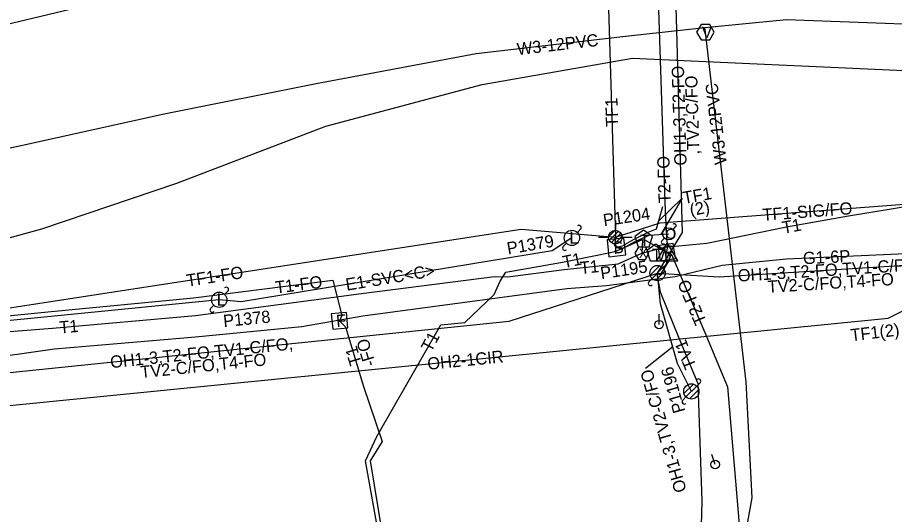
# Model space of a CAD drawing. Extents: x 2336688 to 2352634, y 362473 to 369571.
# Drawn here: x 2351896.3 to 2352182.9, y 368798.3 to 368960.9 of the extents above; entities that cross this region are included whole.
import ezdxf

# ---------------------------------------------------------------- set-up
doc = ezdxf.new("R2010")
doc.units = 0
for name, color, linetype in [('RD_EX_DV_Prop', 7, 'Continuous'), ('RD_EX_DV_TX_Prop', 7, 'Continuous'), ('RD_EX_RW', 7, 'Continuous'), ('RD_EX_RW_TX', 7, 'Continuous'), ('RD_HC_CL_Rel', 7, 'Continuous'), ('RD_HC_Data_Tic', 7, 'Continuous'), ('RD_PD_CstnLmt', 7, 'Continuous'), ('RD_PD_Final_TrvlWay', 7, 'Continuous'), ('RD_PD_FOC', 7, 'Continuous'), ('RD_PD_PatLn2', 7, 'Continuous'), ('RD_PD_PatLn3', 7, 'Continuous'), ('RD_PD_PatLn4', 7, 'Continuous'), ('RD_SHT_ShtClip', 7, 'Continuous'), ('RD_Sketch2', 7, 'Continuous'), ('RD_Sketch5', 7, 'Continuous'), ('RD_Sketch8', 7, 'Continuous')]:
    doc.layers.add(name, color=color, linetype=linetype)

# ---------------------------------------------------------------- blocks, each defined once
blk = doc.blocks.new('GW')
at = {"layer": 'RD_HC_Data_Tic'}
blk.add_line((0, 0), (0, 5), dxfattribs=at)
blk.add_circle((0, 0), 2, dxfattribs=at)

msp = doc.modelspace()

# ---------------------------------------------------------------- linework, layer by layer
at = {"layer": 'RD_EX_RW_TX'}
for points in [[(2352001.58, 369492.45), (2352004.02, 369485.34), (2352012.81, 369439.77), (2352023.11, 369388.83), (2352034.68, 369342.96), (2352043.16, 369279.52), (2352050.69, 369242.38), (2352066.16, 369196.28), (2352079.88, 369147.58), (2352091.56, 369098.6), (2352098.41, 369047.57), (2352103.47, 369016.03), (2352103.73, 369007.69), (2352104.69, 368996.59), (2352107.92, 368897.46), (2352108.57, 368885.58), (2352108.45, 368884.09), (2352110.04, 368883.31), (2352120.9, 368857.81), (2352128.32, 368840.02), (2352133.08, 368783.49)], [(2351885, 368956.88), (2351939.56, 368969.89), (2351988.67, 368980.31), (2352043.04, 368991.24), (2352066.63, 368994.3), (2352086.86, 368995.79), (2352106.62, 368995.87), (2352143.1, 368996.58), (2352187.05, 368996.47), (2352234.49, 368995.02), (2352286.43, 368988.83), (2352336.53, 368982.42)], [(2351854.2, 368855.12), (2351907.65, 368859.27), (2351954.44, 368863.43), (2352008.74, 368870.56), (2352052.2, 368876.14), (2352056.52, 368876.05), (2352074.96, 368878.4), (2352092.6, 368880.26), (2352100.36, 368883.74), (2352107.85, 368885.7), (2352121.63, 368887.01), (2352147.59, 368892.36), (2352167.89, 368895.99), (2352195.79, 368900.53), (2352207.22, 368898.3), (2352213.66, 368891.52), (2352214.78, 368891.59), (2352220.15, 368883.78), (2352239.13, 368881.83), (2352262.16, 368878.52), (2352280.21, 368877.05), (2352321.83, 368870.98)], [(2352023.04, 368743.58), (2352018.61, 368767.78), (2352010.03, 368815.88), (2352013.76, 368823.78), (2352034.6, 368860.37), (2352042.45, 368861.06), (2352052.12, 368870.24), (2352054.08, 368874.63), (2352055.88, 368877.58), (2352074.45, 368880.8), (2352091.57, 368884.28), (2352100.52, 368888.27), (2352100.36, 368883.74)], [(2352100.92, 368888.33), (2352108.45, 368884.09), (2352109.44, 368882.94), (2352109.39, 368881.68), (2352106.38, 368876.68), (2352105.46, 368877.27)], [(2352105.46, 368877.27), (2352105.38, 368876.27), (2352106.29, 368871.12), (2352112.27, 368856.3), (2352118.64, 368841.19), (2352119.94, 368802.65), (2352118.78, 368759.27), (2352108.98, 368715.07), (2352112.43, 368676.89), (2352115.93, 368641.39), (2352118.07, 368629.84), (2352126.4, 368618.98), (2352131.04, 368594.27), (2352141.76, 368542.92), (2352153.06, 368495.22), (2352164.89, 368441.51), (2352174.56, 368395.19)], [(2351800.26, 368708.59), (2351783.98, 368756.59), (2351767.48, 368792.11), (2351762.88, 368809.69), (2351759.04, 368825.42), (2351758.66, 368825.96), (2351759.26, 368827.23), (2351756.66, 368842.63), (2351785.44, 368848.99), (2351806.34, 368852.99), (2351854.03, 368859.38), (2351906.18, 368864.55), (2351953.78, 368869.16), (2351999.38, 368874.93), (2352002.29, 368863.43), (2352001.55, 368861.67), (2352003.47, 368859.64), (2352009.35, 368840.16), (2352015.45, 368822.2), (2352011.56, 368815.85), (2352019.33, 368768.13), (2352023.49, 368743.71)]]:
    msp.add_lwpolyline(points, dxfattribs=at)
for points in [[(2352100.92, 368891.33), (2352098.06, 368889.25), (2352099.15, 368885.9), (2352102.68, 368885.9), (2352103.77, 368889.25)], [(2352102.67, 368883.74), (2352101.51, 368885.74), (2352099.2, 368885.74), (2352098.05, 368883.74), (2352099.2, 368881.74), (2352101.51, 368881.74)], [(2352104.87, 368886.7), (2352102.02, 368884.63), (2352103.11, 368881.27), (2352106.64, 368881.27), (2352107.73, 368884.63)], [(2352110.56, 368886.93), (2352105.61, 368886.2), (2352106.34, 368881.25), (2352111.29, 368881.99)], [(2352003.82, 368864.38), (2351998.84, 368863.94), (2351999.28, 368858.96), (2352004.26, 368859.4)]]:
    msp.add_lwpolyline(points, close=True, dxfattribs=at)
at = {"layer": 'RD_HC_CL_Rel'}
msp.add_lwpolyline([(2351856.12, 368845.07), (2351908.31, 368852.47), (2351954.47, 368856.39), (2351989.24, 368859.76), (2352009.1, 368863.3), (2352075.82, 368872.25), (2352088.74, 368873.22), (2352101.35, 368874.84), (2352111.2, 368876.2), (2352126.61, 368879.82), (2352147.61, 368881.9), (2352189.06, 368883.81), (2352195.59, 368883.03), (2352218.93, 368879.85), (2352230.72, 368877.21), (2352252.22, 368875.78), (2352261.65, 368875.52), (2352280.31, 368872.79), (2352320.53, 368866.38)], dxfattribs=at)
at = {"layer": 'RD_HC_Data_Tic'}
for p, q in [((2352091.68, 368894.52), (2352091.68, 368891.24)), ((2352079.26, 368890.55), (2352080.32, 368891.61)), ((2352089.47, 368889.16), (2352091.55, 368891.24)), ((2352089.72, 368887.99), (2352092.71, 368890.99)), ((2352090.37, 368887.23), (2352093.47, 368890.33)), ((2352110.54, 368891.52), (2352111.38, 368892.37)), ((2352086.15, 368889.02), (2352089.46, 368889.02)), ((2352091.38, 368886.83), (2352093.88, 368889.32)), ((2352093.9, 368889.03), (2352097.21, 368889.03)), ((2352106.86, 368887.84), (2352107.71, 368888.69)), ((2352074.66, 368885.95), (2352075.72, 368887.01)), ((2352091.68, 368886.81), (2352091.68, 368883.52)), ((2352103.05, 368876.63), (2352106.11, 368879.69)), ((2352103.7, 368875.51), (2352107.23, 368879.04)), ((2352107.23, 368879.04), (2352108.29, 368880.1)), ((2352104.82, 368874.86), (2352107.88, 368877.92)), ((2352102.64, 368874.44), (2352103.7, 368875.51)), ((2351963.96, 368870.3), (2351965.02, 368871.36)), ((2351959.36, 368865.71), (2351960.42, 368866.77)), ((2352114.11, 368837.9), (2352117.17, 368840.96)), ((2352114.75, 368836.78), (2352118.29, 368840.31)), ((2352115.87, 368836.13), (2352118.94, 368839.19)), ((2352118.29, 368840.31), (2352119.35, 368841.37)), ((2352113.69, 368835.71), (2352114.75, 368836.78))]:
    msp.add_line(p, q, dxfattribs=at)
for centre, radius in [((2352077.49, 368888.78), 2.5), ((2352091.68, 368889.02), 2.22), ((2352109.12, 368890.1), 2), ((2352105.46, 368877.27), 2.5), ((2351962.19, 368868.54), 2.5), ((2352116.52, 368838.54), 2.5)]:
    msp.add_circle(centre, radius, dxfattribs=at)
for centre, radius, start, end in [((2352110.96, 368892.79), 0.6, 315, 135), ((2352079.79, 368892.14), 0.75, 315, 135), ((2352107.28, 368887.42), 0.6, 135, 315), ((2352075.19, 368885.42), 0.75, 135, 315), ((2352107.76, 368880.63), 0.75, 315, 135), ((2352103.17, 368873.91), 0.75, 135, 315), ((2351964.49, 368871.89), 0.75, 315, 135), ((2351959.89, 368865.18), 0.75, 135, 315), ((2352118.82, 368841.9), 0.75, 315, 135), ((2352114.22, 368835.18), 0.75, 135, 315)]:
    msp.add_arc(centre, radius, start, end, dxfattribs=at)
at = {"layer": 'RD_PD_Final_TrvlWay'}
msp.add_lwpolyline([(2352077.49, 368888.78), (2352071.07, 368884.52), (2351969.42, 368867.88), (2351962.19, 368868.54), (2351879.61, 368860.3)], dxfattribs=at)
at = {"layer": 'RD_PD_FOC'}
for p, q in [((2352105.72, 368894.12), (2352113.54, 368901.79)), ((2352113.54, 368901.79), (2352106.58, 368889.92))]:
    msp.add_line(p, q, dxfattribs=at)
at = {"layer": 'RD_PD_PatLn3'}
msp.add_lwpolyline([(2352108.63, 368887.28), (2352105.16, 368881.28), (2352112.09, 368881.28)], close=True, dxfattribs=at)
at = {"layer": 'RD_PD_PatLn4'}
msp.add_line((2352101.52, 368846.18), (2352110.43, 368853.21), dxfattribs=at)
at = {"layer": 'RD_SHT_ShtClip'}
msp.add_line((2352088.13, 369009.76), (2352091.68, 368889.02), dxfattribs=at)
for points in [[(2352105.46, 368877.27), (2352113.61, 368890.51), (2352109.66, 369030.71), (2352100.79, 369043.46)], [(2352091.68, 368889.02), (2352106.36, 368893.74), (2352203.18, 368901.17), (2352218.4, 368898.75)], [(2351832.35, 368849.22), (2351860.91, 368860.88), (2352060.94, 368891.58), (2352091.68, 368889.02)], [(2351832.35, 368849.22), (2351889.18, 368833.54), (2352180.82, 368862.57), (2352233.45, 368889.14)], [(2352105.46, 368877.27), (2352125.58, 368876.07), (2352233.33, 368882.82), (2352253.13, 368886.52)], [(2351832.35, 368849.22), (2351883.04, 368843.68), (2352056.96, 368861.54), (2352105.46, 368877.27)], [(2352116.52, 368838.54), (2352112.02, 368847.66), (2352106.45, 368867.16), (2352105.46, 368877.27)]]:
    msp.add_lwpolyline(points, dxfattribs=at)
at = {"layer": 'RD_Sketch2'}
for points in [[(2352331.96, 368946.65), (2352284.3, 368952.4), (2352239.4, 368955.94), (2352194.47, 368958.42), (2352147.57, 368960.14), (2352120.89, 368957.46), (2352095.02, 368954.62), (2352046.17, 368949), (2351993.84, 368939.17), (2351944.25, 368929.23), (2351897.87, 368918.99), (2351839.37, 368906.5)], [(2352187.62, 368396.3), (2352174.11, 368454.82), (2352165.61, 368496.3), (2352156.46, 368545.01), (2352143.73, 368594.08), (2352139.42, 368617.5), (2352129.98, 368622.67), (2352124.98, 368624.79), (2352121.55, 368637.11), (2352116.12, 368675.06), (2352115.47, 368708.83), (2352127.49, 368754.37), (2352136.41, 368803.76), (2352134.42, 368841.72), (2352121.13, 368956.04), (2352120.89, 368957.46)]]:
    msp.add_lwpolyline(points, dxfattribs=at)
msp.add_lwpolyline([(2352124.02, 368956.04), (2352122.58, 368958.54), (2352119.69, 368958.54), (2352118.25, 368956.04), (2352119.69, 368953.54), (2352122.58, 368953.54)], close=True, dxfattribs=at)
at = {"layer": 'RD_Sketch5'}
msp.add_lwpolyline([(2351852.53, 368877.54), (2351904.23, 368891.75), (2351948.35, 368906.63), (2351997.09, 368925.32), (2352048.14, 368938.94), (2352097.32, 368947.53), (2352202.88, 368942.76), (2352238.87, 368939.78), (2352282.85, 368935.04), (2352328.83, 368928.03)], dxfattribs=at)
at = {"layer": 'RD_Sketch8'}
for points in [[(2352107.06, 368898.96), (2352105.02, 368891.59), (2352102.25, 368890.51), (2352097.74, 368888.25), (2352093.95, 368886.12), (2352092.04, 368885.65), (2352091.78, 368886.85), (2352091.68, 368889.02)], [(2352092.04, 368885.65), (2352092.88, 368885.41), (2352094.19, 368885.41), (2352097.92, 368887.51), (2352102.72, 368889.64), (2352109.12, 368890.1), (2352109.12, 368890.1)]]:
    msp.add_lwpolyline(points, dxfattribs=at)
msp.add_lwpolyline([(2352094.49, 368888.67), (2352089.02, 368888.1), (2352089.59, 368882.63), (2352095.06, 368883.2)], close=True, dxfattribs=at)

# ---------------------------------------------------------------- block references
at = {"layer": 'RD_HC_Data_Tic', "xscale": 0.6933464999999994}
for p, yscale, rotation in [((2352105.97, 368860.41), 0.6933464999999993, -0.6627014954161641), ((2352124.29, 368814.63), 0.6933464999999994, 17.7401855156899)]:
    msp.add_blockref('GW', p, dxfattribs=dict(at, yscale=yscale, rotation=rotation))

# ---------------------------------------------------------------- texts
at = {"layer": 'RD_EX_DV_Prop'}
msp.add_text('E1-SVC<C>', height=4, rotation=9.3039, dxfattribs=at).set_placement((2352003.87, 368871.49))
at = {"layer": 'RD_EX_DV_TX_Prop'}
for s, rotation, p in [('P1204', 8.4903, (2352087.99, 368892.56)), ('P1379', 9.7315, (2352056.6, 368883.32)), ('P1195', 8.4903, (2352087.09, 368875.25)), ('P1378', 5.6602, (2351963.7, 368859.59)), ('P1196', 105.9348, (2352114.57, 368832.11))]:
    msp.add_text(s, height=4, rotation=rotation, dxfattribs=at).set_placement(p)
at = {"layer": 'RD_EX_RW'}
for s, rotation, p in [('T2-FO', 91.8685, (2352109.83, 368900.2)), ('T1', 10.5238, (2352146.59, 368890.11)), ('T1', 11.49, (2352074.85, 368878.85)), ('T1', 6.0278, (2352080.33, 368876.95)), ('T1-FO', 7.2045, (2351980.76, 368870.56)), ('T2-FO', 113.0615, (2352121.58, 368861.36)), ('T1', 5.0847, (2351910.12, 368857.48)), ('T1', 61.7906, (2352031.47, 368851.15)), ('T1', 106.8141, (2352008.86, 368847.77)), ('-FO', 106.8141, (2352013.45, 368847.38)), ('TV1', 111.9632, (2352118.28, 368846.8))]:
    msp.add_text(s, height=4, rotation=rotation, dxfattribs=at).set_placement(p)
at = {"layer": 'RD_EX_RW_TX'}
for s, height, p in [('T', 3.75, (2352099.69, 368886.1)), ('X', 3, (2352099.41, 368882.24)), ('T', 3.75, (2352103.65, 368881.47))]:
    msp.add_text(s, height=height, dxfattribs=at).set_placement(p)
for rotation, p in [(8.4239, (2352107.62, 368881.95)), (5.079, (2352000.59, 368859.57))]:
    msp.add_text('F', height=4, rotation=rotation, dxfattribs=at).set_placement(p)
at = {"layer": 'RD_HC_Data_Tic'}
for p in [(2352076.68, 368886.85), (2351961.38, 368866.6)]:
    msp.add_text('L', height=4, rotation=360, dxfattribs=at).set_placement(p)
msp.add_text('O', height=3.2, dxfattribs=at).set_placement((2352108.09, 368888.5))
at = {"layer": 'RD_PD_CstnLmt'}
for rotation, p in [(6.5686, (2352059.75, 368948.55)), (96.6265, (2352128.15, 368913.01))]:
    msp.add_text('W3-12PVC', height=4, rotation=rotation, dxfattribs=at).set_placement(p)
at = {"layer": 'RD_PD_FOC'}
for s, rotation, p in [('TF1', 10.2219, (2352114.12, 368899.86)), ('(2)', 10.2219, (2352116.36, 368895.92)), ('TF1(2)', 6.8932, (2352168.8, 368854.94))]:
    msp.add_text(s, height=4, rotation=rotation, dxfattribs=at).set_placement(p)
at = {"layer": 'RD_PD_PatLn2'}
msp.add_text('G1-6P', height=4, rotation=2.6436, dxfattribs=at).set_placement((2352153.1, 368880.15))
at = {"layer": 'RD_PD_PatLn3'}
msp.add_text('U', height=2.4, dxfattribs=at).set_placement((2352107.87, 368882.08))
at = {"layer": 'RD_PD_PatLn4'}
for s, rotation, p in [('OH1-3,T2-FO', 91.6107, (2352114.99, 368912.48)), (',TV2-C/FO', 91.6107, (2352119.17, 368916.09)), ('TF1', 91.6833, (2352092.62, 368925.17)), ('TF1-SIG/FO', 4.387, (2352139.94, 368894.31)), ('OH1-3,T2-FO,TV1-C/FO,', 3.6009, (2352131.83, 368874.45)), ('TF1-FO', 8.7253, (2351951.79, 368872.81)), ('TV2-C/FO,T4-FO', 3.6009, (2352141.58, 368870.78)), ('OH1-3,T2-FO,TV1-C/FO,', 5.8638, (2351926.77, 368846.16)), ('TV2-C/FO,T4-FO', 5.8638, (2351936.66, 368842.87)), ('OH2-1CIR', 5.6834, (2352030.44, 368845.59)), ('OH1-3,TV2-C/FO', 105.9348, (2352115.04, 368806.12))]:
    msp.add_text(s, height=4, rotation=rotation, dxfattribs=at).set_placement(p)
at = {"layer": 'RD_Sketch2'}
msp.add_text('V', height=3.75, dxfattribs=at).set_placement((2352119.92, 368954.16))
at = {"layer": 'RD_Sketch8'}
msp.add_text('S', height=3.89, rotation=5.9379, dxfattribs=at).set_placement((2352091.05, 368883.59))

doc.saveas('drawing.dxf')
